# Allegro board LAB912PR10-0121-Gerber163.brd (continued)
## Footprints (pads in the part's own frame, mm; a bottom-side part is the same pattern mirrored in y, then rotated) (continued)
FIDUCIAL_C40M80
  round 1.016 smd: 1(0,0)
FOX_AS0A621-J4RB-7H_204P-T
  round 1.092 hole 1.092 unplated: (-65.05,-4.1)
  round 1.6 hole 1.6 unplated: (1.75,-4.1)
  oval 0.356x2.007 smd: 1(0,0) 2(-0.3,-8.2) 3(-0.6,0) 4(-0.9,-8.2) 5(-1.2,0) 6(-1.5,-8.2) 7(-1.8,0) 8(-2.1,-8.2) 9(-2.4,0) 10(-2.7,-8.2) 11(-3,0) 12(-3.3,-8.2) 13(-3.6,0) 14(-3.9,-8.2) 15(-4.2,0) 16(-4.5,-8.2) 17(-4.8,0) 18(-5.1,-8.2) 19(-5.4,0) 20(-5.7,-8.2) 21(-6,0) 22(-6.3,-8.2) 23(-6.6,0) 24(-6.9,-8.2) 25(-7.2,0) 26(-7.5,-8.2) 27(-7.8,0) 28(-8.1,-8.2) 29(-8.4,0) 30(-8.7,-8.2) 31(-9,0) 32(-9.3,-8.2) 33(-9.6,0) 34(-9.9,-8.2) 35(-10.2,0) 36(-10.5,-8.2) 37(-10.8,0) 38(-11.1,-8.2) 39(-11.4,0) 40(-11.7,-8.2) 41(-12,0) 42(-12.3,-8.2) 43(-12.6,0) 44(-12.9,-8.2) 45(-13.2,0) 46(-13.5,-8.2) 47(-13.8,0) 48(-14.1,-8.2) 49(-14.4,0) 50(-14.7,-8.2) 51(-15,0) 52(-15.3,-8.2) 53(-15.6,0) 54(-15.9,-8.2) 55(-16.2,0) 56(-16.5,-8.2) 57(-16.8,0) 58(-17.1,-8.2) 59(-17.4,0) 60(-17.7,-8.2) 61(-18,0) 62(-18.3,-8.2) 63(-18.6,0) 64(-18.9,-8.2) 65(-19.2,0) 66(-19.5,-8.2) 67(-19.8,0) 68(-20.1,-8.2) 69(-20.4,0) 70(-20.7,-8.2) 71(-21,0) 72(-21.3,-8.2) 73(-24,0) 74(-24.3,-8.2) 75(-24.6,0) 76(-24.9,-8.2) 77(-25.2,0) 78(-25.5,-8.2) 79(-25.8,0) 80(-26.1,-8.2) 81(-26.4,0) 82(-26.7,-8.2) 83(-27,0) 84(-27.3,-8.2) 85(-27.6,0) 86(-27.9,-8.2) 87(-28.2,0) 88(-28.5,-8.2) 89(-28.8,0) 90(-29.1,-8.2) 91(-29.4,0) 92(-29.7,-8.2) 93(-30,0) 94(-30.3,-8.2) 95(-30.6,0) 96(-30.9,-8.2) 97(-31.2,0) 98(-31.5,-8.2) 99(-31.8,0) 100(-32.1,-8.2) 101(-32.4,0) 102(-32.7,-8.2) 103(-33,0) 104(-33.3,-8.2) 105(-33.6,0) 106(-33.9,-8.2) 107(-34.2,0) 108(-34.5,-8.2) 109(-34.8,0) 110(-35.1,-8.2) 111(-35.4,0) 112(-35.7,-8.2) 113(-36,0) 114(-36.3,-8.2) 115(-36.6,0) 116(-36.9,-8.2) 117(-37.2,0) 118(-37.5,-8.2) 119(-37.8,0) 120(-38.1,-8.2) 121(-38.4,0) 122(-38.7,-8.2) 123(-39,0) 124(-39.3,-8.2) 125(-39.6,0) 126(-39.9,-8.2) 127(-40.2,0) 128(-40.5,-8.2) 129(-40.8,0) 130(-41.1,-8.2) 131(-41.4,0) 132(-41.7,-8.2) 133(-42,0) 134(-42.3,-8.2) 135(-42.6,0) 136(-42.9,-8.2) 137(-43.2,0) 138(-43.5,-8.2) 139(-43.8,0) 140(-44.1,-8.2) 141(-44.4,0) 142(-44.7,-8.2) 143(-45,0) 144(-45.3,-8.2) 145(-45.6,0) 146(-45.9,-8.2) 147(-46.2,0) 148(-46.5,-8.2) 149(-46.8,0) 150(-47.1,-8.2) 151(-47.4,0) 152(-47.7,-8.2) 153(-48,0) 154(-48.3,-8.2) 155(-48.6,0) 156(-48.9,-8.2) 157(-49.2,0) 158(-49.5,-8.2) 159(-49.8,0) 160(-50.1,-8.2) 161(-50.4,0) 162(-50.7,-8.2) 163(-51,0) 164(-51.3,-8.2) 165(-51.6,0) 166(-51.9,-8.2) 167(-52.2,0) 168(-52.5,-8.2) 169(-52.8,0) 170(-53.1,-8.2) 171(-53.4,0) 172(-53.7,-8.2) 173(-54,0) 174(-54.3,-8.2) 175(-54.6,0) 176(-54.9,-8.2) 177(-55.2,0) 178(-55.5,-8.2) 179(-55.8,0) 180(-56.1,-8.2) 181(-56.4,0) 182(-56.7,-8.2) 183(-57,0) 184(-57.3,-8.2) 185(-57.6,0) 186(-57.9,-8.2) 187(-58.2,0) 188(-58.5,-8.2) 189(-58.8,0) 190(-59.1,-8.2) 191(-59.4,0) 192(-59.7,-8.2) 193(-60,0) 194(-60.3,-8.2) 195(-60.6,0) 196(-60.9,-8.2) 197(-61.2,0) 198(-61.5,-8.2) 199(-61.8,0) 200(-62.1,-8.2) 201(-62.4,0) 202(-62.7,-8.2) 203(-63,0) 204(-63.3,-8.2)
  rect 3.505x4.597 smd: 205(-64.45,7.9) 206(1.15,7.9)
H_3P0
  round 3.505 hole 2.997: 1(0,0)
H_3P0X3P8N
  oval 2.997x3.81 hole 2.997x3.81 unplated: (0,0)
H_3P2
  round 3.708 hole 3.2: 1(0,0)
H_3P3
  round 3.81 hole 3.302: 1(0,0)
H_4P0N
  round 3.988 hole 3.988 unplated: (0,0)
INPAQ_HCM2012GA900AE_4P
  rect 0.762x0.508 smd: 1(0,0) 2(1.85,0) 3(1.85,-0.9) 4(0,-0.9)
IP4292CZ10-TBR_XSON10_2P5X1
  oval 0.254x0.889 smd: 1(0,0)
  oval 0.254x0.838 smd: 2(0.5,-0.025) 3(1,-0.025) 4(1.5,-0.025) 5(2,-0.025) 6(2,1.125) 7(1.5,1.125) 8(1,1.125) 9(0.5,1.125) 10(0,1.125)
ISL95833HRTZ-T_TQFN32_4X4
  oval 0.203x0.914 smd: 1(0,0) 2(0.4,0) 3(0.8,0) 4(1.2,0) 5(1.6,0) 6(2,0) 7(2.4,0) 8(2.8,0) 17(2.8,4.077) 18(2.4,4.077) 19(2,4.077) 20(1.6,4.077) 21(1.2,4.077) 22(0.8,4.077) 23(0.4,4.077) 24(0,4.077)
  oval 0.914x0.203 smd: 9(3.438,0.639) 10(3.438,1.039) 11(3.438,1.438) 12(3.438,1.838) 13(3.438,2.239) 14(3.438,2.639) 15(3.438,3.039) 16(3.438,3.438) 25(-0.639,3.438) 26(-0.639,3.039) 27(-0.639,2.639) 28(-0.639,2.239) 29(-0.639,1.838) 30(-0.639,1.438) 31(-0.639,1.039) 32(-0.639,0.639)
  rect 2.692x2.692 smd: 33(1.4,2.039)
JUMP_43X39
  custom 0.191x0.191 smd: 1(0,0) 2(0.914,0)
JUMP_43X79
  custom 0.188x0.188 smd: 1(0,0) 2(1.1,0)
JUMP_43X118
  custom 0.187x0.187 smd: 1(0,0) 2(1.1,0)
JXT_FP202DH-004M10M_4P
  oval 0.61x1.448 smd: 1(0,0) 2(1,0) 3(2,0) 4(3,0)
  rect 2.159x2.21 smd: 5(-2.825,-3.125) 6(5.825,-3.125)
JXT_FP202DH-008M10M_8P
  oval 0.61x1.448 smd: 1(0,0) 2(1,0) 3(2,0) 4(3,0) 5(4,0) 6(5,0) 7(6,0) 8(7,0)
  rect 2.159x2.21 smd: 9(-2.825,-3.125) 10(9.825,-3.125)
KB9022QC_LQFP128_14X14
  oval 1.753x0.203 smd: 1(0,0) 2(0,-0.4) 3(0,-0.8) 4(0,-1.2) 5(0,-1.6) 6(0,-2) 7(0,-2.4) 8(0,-2.8) 9(0,-3.2) 10(0,-3.6) 11(0,-4) 12(0,-4.4) 13(0,-4.8) 14(0,-5.2) 15(0,-5.6) 16(0,-6) 17(0,-6.4) 18(0,-6.8) 19(0,-7.2) 20(0,-7.6) 21(0,-8) 22(0,-8.4) 23(0,-8.8) 24(0,-9.2) 25(0,-9.6) 26(0,-10) 27(0,-10.4) 28(0,-10.8) 29(0,-11.2) 30(0,-11.6) 31(0,-12) 32(0,-12.4) 65(15.654,-12.4) 66(15.654,-12) 67(15.654,-11.6) 68(15.654,-11.2) 69(15.654,-10.8) 70(15.654,-10.4) 71(15.654,-10) 72(15.654,-9.6) 73(15.654,-9.2) 74(15.654,-8.8) 75(15.654,-8.4) 76(15.654,-8) 77(15.654,-7.6) 78(15.654,-7.2) 79(15.654,-6.8) 80(15.654,-6.4) 81(15.654,-6) 82(15.654,-5.6) 83(15.654,-5.2) 84(15.654,-4.8) 85(15.654,-4.4) 86(15.654,-4) 87(15.654,-3.6) 88(15.654,-3.2) 89(15.654,-2.8) 90(15.654,-2.4) 91(15.654,-2) 92(15.654,-1.6) 93(15.654,-1.2) 94(15.654,-0.8) 95(15.654,-0.4) 96(15.654,0)
  oval 0.203x1.753 smd: 33(1.627,-14.027) 34(2.027,-14.027) 35(2.427,-14.027) 36(2.827,-14.027) 37(3.227,-14.027) 38(3.627,-14.027) 39(4.027,-14.027) 40(4.427,-14.027) 41(4.827,-14.027) 42(5.227,-14.027) 43(5.627,-14.027) 44(6.027,-14.027) 45(6.427,-14.027) 46(6.827,-14.027) 47(7.227,-14.027) 48(7.627,-14.027) 49(8.027,-14.027) 50(8.427,-14.027) 51(8.827,-14.027) 52(9.227,-14.027) 53(9.627,-14.027) 54(10.027,-14.027) 55(10.427,-14.027) 56(10.827,-14.027) 57(11.227,-14.027) 58(11.627,-14.027) 59(12.027,-14.027) 60(12.427,-14.027) 61(12.827,-14.027) 62(13.227,-14.027) 63(13.627,-14.027) 64(14.027,-14.027) 97(14.027,1.627) 98(13.627,1.627) 99(13.227,1.627) 100(12.827,1.627) 101(12.427,1.627) 102(12.027,1.627) 103(11.627,1.627) 104(11.227,1.627) 105(10.827,1.627) 106(10.427,1.627) 107(10.027,1.627) 108(9.627,1.627) 109(9.227,1.627) 110(8.827,1.627) 111(8.427,1.627) 112(8.027,1.627) 113(7.627,1.627) 114(7.227,1.627) 115(6.827,1.627) 116(6.427,1.627) 117(6.027,1.627) 118(5.627,1.627) 119(5.227,1.627) 120(4.827,1.627) 121(4.427,1.627) 122(4.027,1.627) 123(3.627,1.627) 124(3.227,1.627) 125(2.827,1.627) 126(2.427,1.627) 127(2.027,1.627) 128(1.627,1.627)
KC_FBMA-L11-160808-800LMT_2P
  rect 0.889x1.092 smd: 1(0,0) 2(1.5,0)
KC_FBMA-L11-201209-221LMA30_2P
  rect 0.838x1.397 smd: 1(0,0) 2(1.65,0)
L_4X4X2_F_2P-NPM
  rect 1.194x3.708 smd: 1(0,0) 2(2.8,0)
L_7X7X3_M_2P
  rect 2.362x3.505 smd: 1(0,0) 2(6.05,0)
LBAV70WT1G_SC70-3
  oval 0.711x0.889 smd: 1(0,0) 2(-0.65,-1.9) 3(0.65,-1.9)
LED_12-21C-T3D-CM2P1B18X-2C_3P
  rect 0.991x0.787 smd: 1(0,0) 2(-2.8,0)
  rect 0.991x0.61 smd: 3(-1.4,0.4)
LED_12-22A-S2ST3D-C30-2C_3P
  rect 0.991x1.499 smd: 1(0,0) 3(-3,0)
  rect 0.889x0.889 smd: 2(-1.5,-0.65)
LOTES_AAA-BAT-054-K01_2P
  round 0.787 hole 0.787 unplated: (-14.5,-8)
  round 1.194 hole 1.194 unplated: (-14.5,8)
  rect 2.007x3.988 smd: 1(0,0) 2(-30.1,0)
MDV1527URH_POWERDFN33-8-5
  oval 0.406x0.61 smd: 1(0,0) 2(0.65,0) 3(1.3,0) 4(1.95,0)
  custom 0.65x0.65 smd: 5(0.975,1.475)
MDV1528URH_PDFN33-8-5
  oval 0.406x0.61 smd: 1(0,0) 2(0.65,0) 3(1.3,0) 4(1.95,0)
  custom 0.65x0.65 smd: 5(0.975,1.475)
MESS138W-G_SOT323-3
  oval 0.711x0.889 smd: 1(0,0) 2(-0.65,-1.9) 3(0.65,-1.9)
MMST3904-7-F_SOT323-3
  oval 0.711x0.889 smd: 1(0,0) 2(0.65,1.9) 3(-0.65,1.9)
MOLEX_52435-2671_26P-T
  oval 0.305x0.787 smd: 1(0,0) 2(0.5,0) 3(1,0) 4(1.5,0) 5(2,0) 6(2.5,0) 7(3,0) 8(3.5,0) 9(4,0) 10(4.5,0) 11(5,0) 12(5.5,0) 13(6,0) 14(6.5,0) 15(7,0) 16(7.5,0) 17(8,0) 18(8.5,0) 19(9,0) 20(9.5,0) 21(10,0) 22(10.5,0) 23(11,0) 24(11.5,0) 25(12,0) 26(12.5,0)
  custom 0.597x0.597 smd: 27(-2.45,-1.925) 28(14.95,-1.925)
MURAT_BLM15AG102SN1D_2P
  rect 0.457x0.508 smd: 1(0,0) 2(0.85,0)
MURAT_BLM15BB221SN1D_2P
  rect 0.508x0.762 smd: 1(0,0) 2(0.75,0)
MURAT_BLM15BD601SN1D_2P
  rect 0.508x0.762 smd: 1(0,0) 2(0.75,0)
MURAT_BLM41PG600SN1L_2P
  rect 1.194x2.108 smd: 1(0,0) 2(3.8,0)
MURAT_BLM41PG600SN1L_2P-NPM
  rect 1.194x2.108 smd: 1(0,0) 2(3.8,0)
NCT3942S_SO8
  oval 0.635x1.854 smd: 1(0,0) 2(1.27,0) 3(2.54,0) 4(3.81,0) 5(3.81,5.165) 6(2.54,5.165) 7(1.27,5.165) 8(0,5.165)
PANAS_ETQP4LR15AFM_4P
  custom 0.686x0.686 smd: 1(0,0) 4(8.357,0)
  rect 2.21x0.508 smd: 2(1.448,0) 3(6.909,0)
PESD5V0U2BT_SOT23-3
  oval 1.016x1.524 smd: 1(0,0) 2(0.965,2.083) 3(-0.965,2.083)
R0402_0OHM
  rect 0.508x0.559 smd: 1(0,0) 2(0.914,0)
R0603_0OHM
  rect 0.635x0.889 smd: 1(0,0) 2(1.397,0)
R0805_0OHM
  rect 0.813x1.397 smd: 1(0,0) 2(1.702,0)
R_0402
  rect 0.508x0.559 smd: 1(0,0) 2(0.914,0)
R_0603
  rect 0.635x0.889 smd: 1(0,0) 2(1.397,0)
R_1206
  rect 1.016x1.651 smd: 1(0,0) 2(2.667,0)
R_1206_4P-D
  custom 0.445x0.445 smd: 1(0,0) 4(5.004,0)
  custom 0.114x0.114 smd: 2(1.194,0) 3(3.81,0)
RB751V-40_SOD323-2
  rect 0.787x0.889 smd: 1(0,0) 2(2.14,0)
RHU002N06_SOT323-3
  oval 0.813x0.914 smd: 1(0,0) 2(0.65,1.6) 3(-0.65,1.6)
RP_0804_8P4R
  oval 0.66x0.254 smd: 1(0,0) 2(0,-0.5) 3(0,-1) 4(0,-1.5) 5(1.15,-1.5) 6(1.15,-1) 7(1.15,-0.5) 8(1.15,0)
RT8207MZQW_WQFN20_3X3
  oval 0.203x0.889 smd: 1(0,0) 2(0.4,0) 3(0.8,0) 4(1.2,0) 5(1.6,0) 11(1.6,3.1) 12(1.2,3.1) 13(0.8,3.1) 14(0.4,3.1) 15(0,3.1)
  oval 0.889x0.203 smd: 6(2.35,0.75) 7(2.35,1.15) 8(2.35,1.55) 9(2.35,1.95) 10(2.35,2.35) 16(-0.75,2.35) 17(-0.75,1.95) 18(-0.75,1.55) 19(-0.75,1.15) 20(-0.75,0.75)
  rect 1.702x1.702 smd: 21(0.8,1.55)
RTS5179-GR_QFN24_4X4
  oval 0.254x0.889 smd: 1(0,0) 2(0.5,0) 3(1,0) 4(1.5,0) 5(2,0) 6(2.5,0) 13(2.5,4.1) 14(2,4.1) 15(1.5,4.1) 16(1,4.1) 17(0.5,4.1) 18(0,4.1)
  oval 0.889x0.254 smd: 7(3.3,0.8) 8(3.3,1.3) 9(3.3,1.8) 10(3.3,2.3) 11(3.3,2.8) 12(3.3,3.3) 19(-0.8,3.3) 20(-0.8,2.8) 21(-0.8,2.3) 22(-0.8,1.8) 23(-0.8,1.3) 24(-0.8,0.8)
  rect 2.261x2.261 smd: 25(1.25,2.05)
SHORTPADS
  custom 0.19x0.19 smd: 1(-0.483,0) 2(0.483,0)
SI3456BDV-T1-E3_TSOP6
  oval 0.508x1.448 smd: 1(0,0) 2(1,0) 3(2,0) 4(2,2.425) 5(1,2.425) 6(0,2.425)
SI4459ADY-T1-GE3_SO8
  oval 0.635x1.727 smd: 1(0,0) 2(1.27,0) 3(2.54,0) 4(3.81,0) 5(3.81,5.285) 6(2.54,5.285) 7(1.27,5.285) 8(0,5.285)
SIS412DN-T1-GE3_POWERPAK8-5
  oval 0.406x0.991 smd: 1(0,0) 2(0.66,0) 3(1.32,0) 4(1.98,0)
  custom 0.559x0.559 smd: 5(0.99,2.247)
SN74LVC1G07DCKR_SC70-5
  oval 0.381x0.864 smd: 1(0,0) 2(0.65,0) 3(1.3,0) 4(1.3,1.74) 5(0,1.74)
SUYIN_200277GR008M270ZR_8P-T
  round 1.6 hole 0.991: 1(0,0) 2(2,0) 3(4,0) 4(6,0) 5(8,0) 6(10,0) 7(12,0) 8(14,0)
  oval 1.397x3.454 hole 0.787x2.845: 9(17.125,0) 10(-3.125,0)
SW_SMT1-05-A_4P
  rect 0.61x0.991 smd: 1(0,0) 2(0,-4.4) 3(3.7,0) 4(3.7,-4.4)
  rect 0.457x0.991 smd: 5(-0.675,-2.2) 6(4.375,-2.2)
SY6288C20AAC_SOT23-5
  oval 0.559x0.787 smd: 1(0,0) 2(0.95,0) 3(1.9,0) 4(1.9,2.4) 5(0,2.4)
SY6288D20AAC_SOT23-5
  oval 0.559x0.787 smd: 1(0,0) 2(0.95,0) 3(1.9,0) 4(1.9,2.4) 5(0,2.4)
SY8032ABC_SOT23-6
  oval 0.61x0.991 smd: 1(0,0) 2(0.95,0) 3(1.9,0) 4(1.9,2.4) 5(0.95,2.4) 6(0,2.4)
TAI-T_HCB2012KF-121T50_2P
  rect 0.991x0.991 smd: 1(0,0) 2(2,0)
TAI_PSDATG-11GLBS1NN4H0_11P-T
  round 1.194 hole 1.194 unplated: (-18.375,-2.925)
  round 1.702 hole 1.702 unplated: (2.625,-2.925)
  oval 0.991x1.753 smd: 1(0,0) 2(-2.5,0) 3(-5,0) 4(-7.5,0) 5(-10,0) 6(-12.5,0) 7(-15,0) 8(-16.63,0) 9(2.5,0)
  oval 0.711x1.753 smd: 10(-17.93,0) 11(-19.13,0)
  rect 1.473x2.794 smd: 12(-20.525,-1.925) 15(4.425,-1.925)
  oval 1.194x3.912 hole 0.61x3.404: 13(-19.975,-11.775) 14(6.225,-11.775)
TAITW_PUBAUN-09FLBS1NN4H0_9P-T
  round 1.295 hole 0.711: 1(0,0) 2(-2.5,0) 3(-4.5,0) 4(-7,0) 5(-7.5,-1.5) 6(-5.5,-1.5) 7(-3.5,-1.5) 8(-1.5,-1.5) 9(0.5,-1.5)
  oval 1.295x2.997 hole 0.711x2.388: 10(2.9,-0.75) 11(-9.9,-0.75)
  oval 1.295x2.21 hole 0.711x1.6: 12(-11.35,-9.2) 13(4.35,-9.2)
TCS20DLR_SOT23F-3
  oval 0.787x0.889 smd: 1(0,0) 2(-0.95,-2.1) 3(0.95,-2.1)
TOKO_1239AS-H-1R0M-P2_2P
  rect 0.787x2.007 smd: 1(0,0) 2(2,0)
TPC12
  round 0.305 smd: 1(0,0)
TPS51225CRUKR_QFN20_3X3
  oval 0.203x0.889 smd: 1(0,0) 2(0.4,0) 3(0.8,0) 4(1.2,0) 5(1.6,0) 11(1.6,3.1) 12(1.2,3.1) 13(0.8,3.1) 14(0.4,3.1) 15(0,3.1)
  oval 0.889x0.203 smd: 6(2.35,0.75) 7(2.35,1.15) 8(2.35,1.55) 9(2.35,1.95) 10(2.35,2.35) 16(-0.75,2.35) 17(-0.75,1.95) 18(-0.75,1.55) 19(-0.75,1.15) 20(-0.75,0.75)
  rect 1.702x1.702 smd: 21(0.8,1.55)
TVNST52302AB0_SOT523-3
  oval 0.508x0.559 smd: 1(0,0) 2(-0.5,-1.4) 3(0.5,-1.4)
W25Q64DWSSIG_SO8
  oval 0.635x1.676 smd: 1(0,0) 2(1.27,0) 3(2.54,0) 4(3.81,0) 5(3.81,7.25) 6(2.54,7.25) 7(1.27,7.25) 8(0,7.25)
Y_5YEA12000122IFA2Q3_4P
  rect 1.295x1.194 smd: 1(0,0) 2(2.2,0) 3(2.2,1.7) 4(0,1.7)
Y_7V25000014_4P
  rect 1.397x1.194 smd: 1(0,0) 2(2.2,0) 3(2.2,1.7) 4(0,1.7)
Y_CM7V-12520_2P
  rect 0.991x1.803 smd: 1(0,0) 2(2.5,0)
YSLC05CH_SOT23-3
  oval 1.016x1.524 smd: 1(0,0) 2(0.965,2.083) 3(-0.965,2.083)

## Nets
1.0VS_GATE: C1131.1 Q70.1 R1061.1 U60.4
1.8VS_ON: C1125.2 R1055.1 U12.2
1.35VS_ON: C1128.2 R1056.1 U12.4
3VS_ON: C980.1 R927.1 U11.2
5VS_ON: C979.2 R926.2 U11.4
+0.675VS: CD24.1 CD25.1 CD26.1 CD27.1 CD28.1 CD29.1 CD43.1 CD44.1 CD45.1 CD46.1 JDIMM2.203 JDIMM2.204 PJP202.2 R2314.1
+0.675VSP: PC208.1 PC209.1 PJP202.1 PU200.2 PU200.20
+1.0VALW: C1034.2 C1035.2 C1036.2 C1037.2 C1039.2 C1074.1 C1129.2 PJP303.2 U60.5 U60.6 U60.7 U60.8 USOC1.B6 USOC1.C3 USOC1.C5 USOC1.U22 USOC1.V18 USOC1.V22 USOC1.Y19
+1.0VALWP: PC308.1 PC310.1 PC311.1 PJP303.1 PL301.2 PR307.1
+1.0VALWP_ON: PC309.1 PR305.1 PR308.2 PU301.1
+1.0VS: C1043.2 C1044.2 C1046.2 C1047.2 C1048.2 C1049.2 C1050.2 C1052.2 C1056.2 C1057.2 C1059.2 C1060.2 C1061.2 C1062.2 C1064.2 C1066.2 C1068.2 C1069.2 C1070.2 C1071.2 C1072.2 C1130.2 PC523.1 PR525.2 PR526.2 PR527.2 R1052.2 RC15.2 RC27.1 U60.1 U60.2 U60.3 USOC1.AA36 USOC1.AD35 USOC1.AF16 USOC1.AF18 USOC1.AF21 USOC1.AF35 USOC1.AF36 USOC1.AG21 USOC1.AJ18 USOC1.AJ36 USOC1.AK18 USOC1.AK19 USOC1.AK21 USOC1.AK35 USOC1.AK36 USOC1.AM16 USOC1.AM18 USOC1.AM21 USOC1.AN18 USOC1.AN19 USOC1.AN21 USOC1.AN25 USOC1.AN29 USOC1.AN30 USOC1.BJ6 USOC1.G1 USOC1.M14 USOC1.U18 USOC1.U19 USOC1.V24 USOC1.V32 USOC1.Y18 USOC1.Y22 USOC1.Y24 USOC1.Y35 USOC1.Y36
+1.0VS_R: Q71.1 R1052.1
+1.05V_PGOOD: T210.1(TP-1) UE1.106
+1.05VS: C1038.1 C1040.1 C1041.1 C1042.1 PJP301.2 R2315.1 RC100.1 USOC1.AA33 USOC1.AF33 USOC1.AG33 USOC1.AG35 USOC1.U33 USOC1.U35 USOC1.V33
+1.5VS: C1058.1 PJP405.2 RA8.1 UA1.9 USOC1.AM32
+1.05VS_SOC: RC100.2 USOC1.AC32 USOC1.Y32
+1.5VSP: PC413.1 PC414.1 PJP405.1 PR410.1 PU402.3 PU402.4
+1.05VSP: PC301.1 PC302.1 PC303.1 PJP301.1 PL300.2 PR302.1
+1.05VSP_ON: PC304.1 PR300.2 PR303.1 PU300.1
+1.8VALW: C1045.1 C1145.2 JDB1.16 PJP401.2 PJP404.1 R3.1 R4.1 R7.1 R32.2 R34.2 R36.2 RC21.1 RC44.1 RC46.1 RC61.1 RC62.1 RC63.1 RC65.1 RC99.1 RE21.1 RE25.1 RE34.1 RP65.5 RP65.6 RP65.7 RP65.8 RP66.1 RP66.2 U12.1 UC5.5 USOC1.AA18 USOC1.N20 USOC1.U24 USOC1.U25 USOC1.V25
+1.8VALWP: PC401.1 PC402.1 PC403.1 PJP401.1 PL400.2 PR402.1
+1.8VS: C1051.1 C1053.1 C1054.1 C1055.1 C1147.1 JP38.2 Q57.2 Q58.2 QC2.2 QC3.2 QC4.2 QE7.2 QE8.2 QE10.2 QE11.2 QE12.2 R8.1 R376.1 R3406.1 RC8.2 RC10.1 RC16.1 RC17.1 RC18.1 RC43.1 RC102.1 RE30.1 RE31.1 RP15.3 RP15.4 RP63.5 RP63.6 RP63.7 RP63.8 RP68.5 RP68.6 RP68.7 RX2.1 RX3.1 RX41.1 UC10.5 USOC1.AM30 USOC1.AN32 USOC1.U38
+1.8VS_OUT: C1124.2 JP38.1 U12.10
+1.8VSP_ON: PC404.1 PR400.2 PR403.1 PU400.1
+1.35V: C1146.2 CD4.1 CD5.1 CD6.1 CD7.1 CD8.1 CD9.1 CD10.1 CD11.1 CD12.1 CD13.1 CD14.1 CD15.1 CD16.1 CD17.1 CD18.1 CD19.1 CD20.1 CD33.1 CD34.1 CD35.1 CD36.1 CD37.1 CD38.1 CD39.1 CD40.1 CD41.1 CD42.1 CD62.2 JDIMM2.75 JDIMM2.76 JDIMM2.81 JDIMM2.82 JDIMM2.87 JDIMM2.88 JDIMM2.93 JDIMM2.94 JDIMM2.99 JDIMM2.100 JDIMM2.105 JDIMM2.106 JDIMM2.111 JDIMM2.112 JDIMM2.117 JDIMM2.118 JDIMM2.123 JDIMM2.124 JP14.2 JP15.2 PC902.1 PC904.1 PC906.1 PC908.1 PJP201.2 R1027.1 R1029.1 RC6.1 RD3.1 U12.5
+1.35V_SOC: CC29.2 CC30.2 CC31.2 CC32.2 CC33.1 CC34.1 JP14.1 JP15.1 RC54.1 USOC1.A48 USOC1.AK38 USOC1.AM38 USOC1.AV41 USOC1.AV42 USOC1.BB46 USOC1.BD49 USOC1.BD52 USOC1.BD53 USOC1.BF44 USOC1.BG51 USOC1.BJ48 USOC1.C51 USOC1.D44 USOC1.F49 USOC1.F52 USOC1.F53 USOC1.H46 USOC1.M41 USOC1.M42 USOC1.V38 USOC1.Y38
+1.35VP: PC201.1 PC216.2 PJP201.1 PL200.1 PR204.2 PR210.1 PU200.5 PU200.19
+1.35VS: C1148.1 CC38.1 CC39.1 CC40.1 CC41.1 CC42.1 CC43.1 CC44.1 CC45.1 CC46.1 CC47.1 JP39.2 RC30.1 RC67.1 USOC1.AA25 USOC1.AD36 USOC1.AF19 USOC1.AG18 USOC1.AG19 USOC1.AG32 USOC1.AJ19 USOC1.U36 USOC1.V36
+1.35VS_OUT: C1126.2 JP39.1 U12.6
+3V_HUB: R1047.1 R1050.1 R1051.1
+3VALW: C1143.2 C2316.1 C2318.1 CE61.2 PJP101.2 PJP300.1 PJP302.1 PJP400.1 PR4.2 PR7.2 PR510.1 PR530.2 R1022.1 R2356.2 RA17.1 RE2.2 RE6.2 U11.1 UC7.5
+3VALW_EC: C1.1 C2.1 CE1.1 CE2.1 CE5.2 CE6.2 JPWR.1 LE1.1 R1.1 R488.1 R696.2 R697.2 RE3.2 RE6.1 RE11.2 RP36.5 RP36.6 U70.2 UE1.22 UE1.33 UE1.96 UE1.125
+3VALW_SOC: C1063.1 C1065.1 C1067.1 R1022.2 USOC1.N18 USOC1.N22 USOC1.P18
+3VALWP: PC102.1 PC106.1 PJP101.1 PL100.1 PR100.1 PR106.1
+3VLP: JP12.1 PC105.1 PU100.3 RE49.2 UE1.111
+3VS: C1075.1 C2323.1 C2324.1 C2498.1 CA57.1 CA58.1 CA59.1 CA60.1 CD30.1 CD31.1 CD47.1 CD62.1 CX7.1 JDIMM2.199 JP36.2 Q14.5 Q6103.2 R9.2 R11.2 R122.1 R1023.1 R2448.1 R2449.1 R2451.1 R6110.1 RA1.1 RA2.1 RA18.2 RA54.2 RA155.2 RC20.1 RC53.1 RC68.1 RE50.1 RM7.1 RP36.7 RP36.8 RP54.5 RP54.6 RP54.7 RP54.8 RR9.2 RS7.1 RT17.1 RV299.2 RX10.1 RX12.1 RX27.2 U2407.1 UA1.1 UA1.36 UX4.5
+3VS_CAM: JEDP.32 RX27.1
+3VS_CARD: CR1.1 CR2.1 RR9.1 UR1.4
+3VS_LCDIN: CX9.1 RV299.1 UX1.4 UX1.5
+3VS_OUT: C1138.2 JP36.1 U11.10
+3VS_SOC: R1023.2 USOC1.AN24 USOC1.AN27
+3VS_TP: CE59.1 JTP.1 RE9.1 RE10.1 RE17.1 RE19.1 RE20.1 RE26.2 RE28.1 UE4.7 UE4.8
+3VS_TPIN: RE2.1 RE26.1 UE4.1 UE4.2 UE4.4
+3VS_WLAN_NGFF: CM4.1 CM5.1 CM6.1 CM7.1 CM8.1 CM9.1 JNGFF.2 JNGFF.4 JNGFF.64 JNGFF.66 QM30.2 R490.1 RM7.2 RM110.1
+5V_AUDIO: CA51.1 CA71.1 RV59.2 UA1.26
+5V_HDD: CS5.1 CS6.1 CS7.1 JHDD.1 JHDD.2 JHDD.3 JP13.1
+5V_HUB: C1117.1 C1118.1 R1045.2 R1046.1 R1053.2 U58.20
+5V_PVDD: CA53.1 CA54.1 CA55.1 CA56.1 RV54.2 UA1.41 UA1.46
+5V_USB_PWR1: CI1.1 CI2.1 CI40.1 JUSB1.1 UI5.1
+5V_USB_PWR2: CI19.1 JIO1.11 JIO1.12 JIO1.13 JIO1.14 JIO1.15 R1053.1 UI4.1
+5VALW: C1120.1 C1144.2 C2305.1 C2306.1 CI6.1 CI7.1 CI12.1 CI14.1 CI18.1 PC411.1 PC715.1 PJP100.2 PR3.1 PR203.1 PR209.1 PR518.2 PR519.1 PR524.1 PU402.6 PU700.11 Q6101.3 Q6102.3 R10.1 R1045.1 R1061.2 U11.3 U11.5 U12.3 UI4.5 UI5.5
+5VALWP: PC103.1 PC107.2 PJP100.1 PL101.2 PR101.2 PU100.14
+5VS: C2307.1 C2308.1 CE25.1 CS13.1 FX1.2 JP7.1 JP13.2 JP37.2 Q6104.3 QS2.1 QS2.2 QS2.5 QS2.6 RE60.1 RV54.1 RV59.1 RX28.2 UE3.1 UE3.2
+5VS_ODD: CS10.1 CS11.1 CS12.1 JODD1.10 JODD1.11 JODD1.12 JODD1.13 JODD1.14 JODD1.15 RS12.2
+5VS_ODD_R1: JP7.2 QS2.4 RS12.1
+5VS_OUT: C1139.2 JP37.1 U11.6
+5VS_TOUCH: CX49.1 CX50.1 JEDP.40 RX24.1 RX30.1 RX39.1 RX40.1 RX42.1 UX3.1
+V18R: CE16.1 RE21.2 UE1.124
+VCC_3IN1: CR7.1 CR8.1 JREAD.4 UR1.5
+VCC_LPC: RE25.2 UE1.9
+VCC_LPC_SOC: C1073.1 RC102.2 USOC1.AM27
B+_3/5V: PC108.1 PC109.1 PC110.1 PC111.1 PJP102.2 PL102.2 PQ101.5 PQ102.5 PR111.1
GND: C1.2 C2.2 C3.1 C967.1 C976.1 C979.1 C980.2 C1034.1 C1035.1 C1036.1 C1037.1 C1038.2 C1039.1 C1040.2 C1041.2 C1042.2 C1043.1 C1044.1 C1045.2 C1046.1 C1047.1 C1048.1 C1049.1 C1050.1 C1051.2 C1052.1 C1053.2 C1054.2 C1055.2 C1056.1 C1057.1 C1058.2 C1059.1 C1060.1 C1061.1 C1062.1 C1063.2 C1064.1 C1065.2 C1066.1 C1067.2 C1068.1 C1069.1 C1070.1 C1071.1 C1072.1 C1073.2 C1074.2 C1075.2 C1076.2 C1078.2 C1117.2 C1118.2 C1119.2 C1120.2 C1121.2 C1122.1 C1123.1 C1124.1 C1125.1 C1126.1 C1127.1 C1128.1 C1129.1 C1130.1 C1131.2 C1132.2 C1133.2 C1138.1 C1139.1 C1143.1 C1144.1 C1145.1 C1146.1 C1147.2 C1148.2 C2305.2 C2306.2 C2307.2 C2308.2 C2316.2 C2318.2 C2323.2 C2324.2 C2498.2 CA1.2 CA2.2 CA21.2 CA22.2 CA25.1 CA29.2 CA30.2 CA31.2 CA32.2 CA53.2 CA54.2 CA55.2 CA56.2 CA57.2 CA58.2 CA59.2 CA60.2 CA64.1 CA69.2 CC1.2 CC2.2 CC7.2 CC8.1 CC9.2 CC10.2 CC11.2 CC12.2 CC13.2 CC14.2 CC15.2 CC16.2 CC17.2 CC18.2 CC19.2 CC20.1 CC21.2 CC22.2 CC23.2 CC24.1 CC25.2 CC26.2 CC27.2 CC28.2 CC29.1 CC30.1 CC31.1 CC32.1 CC33.2 CC34.2 CC35.2 CC36.2 CC38.2 CC39.2 CC40.2 CC41.2 CC42.2 CC43.2 CC44.2 CC45.2 CC46.2 CC47.2 CC49.2 CC50.2 CC51.2 CC52.2 CC53.2 CC54.2 CC56.2 CC57.2 CC59.2 CC61.2 CC63.2 CC65.2 CD1.2 CD2.2 CD3.2 CD4.2 CD5.2 CD6.2 CD7.2 CD8.2 CD9.2 CD10.2 CD11.2 CD12.2 CD13.2 CD14.2 CD15.2 CD16.2 CD17.2 CD18.2 CD19.2 CD20.2 CD21.2 CD22.2 CD24.2 CD25.2 CD26.2 CD27.2 CD28.2 CD29.2 CD30.2 CD31.2 CD32.2 CD33.2 CD34.2 CD35.2 CD36.2 CD37.2 CD38.2 CD39.2 CD40.2 CD41.2 CD42.2 CD43.2 CD44.2 CD45.2 CD46.2 CD47.2 CE1.2 CE2.2 CE5.1 CE6.1 CE8.2 CE10.2 CE12.2 CE16.2 CE18.1 CE20.2 CE23.2 CE24.2 CE25.2 CE26.2 CE27.2 CE28.2 CE29.2 CE31.2 CE32.2 CE34.2 CE35.2 CE36.2 CE59.2 CE60.2 CE61.1 CI1.2 CI2.2 CI6.2 CI7.2 CI12.2 CI13.2 CI14.2 CI15.2 CI17.2 CI18.2 CI19.2 CI26.2 CI40.2 CLIP1.1(TP-1) CLIP2.1(TP-1) CLIP3.1(TP-1) CLRP1.2 CM4.2 CM5.2 CM6.2 CM7.2 CM8.2 CM9.2 CR1.2 CR2.2 CR3.1 CR4.1 CR6.2 CR7.2 CR8.2 CR9.2 CR11.2 CS5.2 CS6.2 CS7.2 CS10.2 CS11.2 CS12.2 CS13.2 CS16.2 CS17.2 CX5.2 CX6.2 CX7.2 CX8.2 CX9.2 CX10.2 CX11.2 CX21.2 CX22.2 CX49.2 CX50.2 CX51.2 CX52.2 D25.1 D26.1 D27.1 DE3.1 DI1.3 DI1.8 EC6104.2 H1.1(TP-1) H3.1(TP-1) H4.1(TP-1) H5.1(TP-1) H6.1(TP-1) H9.1(TP-1) H10.1(TP-1) H11.1(TP-1) H12.1(TP-1) JDB1.3 JDB1.6 JDB1.9 JDB1.19 JDB1.25 JDB1.27 JDB1.28 JDIMM2.2 JDIMM2.3 JDIMM2.8 JDIMM2.9 JDIMM2.13 JDIMM2.14 JDIMM2.19 JDIMM2.20 JDIMM2.25 JDIMM2.26 JDIMM2.31 JDIMM2.32 JDIMM2.37 JDIMM2.38 JDIMM2.43 JDIMM2.44 JDIMM2.48 JDIMM2.49 JDIMM2.54 JDIMM2.55 JDIMM2.60 JDIMM2.61 JDIMM2.65 JDIMM2.66 JDIMM2.71 JDIMM2.72 JDIMM2.127 JDIMM2.128 JDIMM2.133 JDIMM2.134 JDIMM2.138 JDIMM2.139 JDIMM2.144 JDIMM2.145 JDIMM2.150 JDIMM2.151 JDIMM2.155 JDIMM2.156 JDIMM2.161 JDIMM2.162 JDIMM2.167 JDIMM2.168 JDIMM2.172 JDIMM2.173 JDIMM2.178 JDIMM2.179 JDIMM2.184 JDIMM2.185 JDIMM2.189 JDIMM2.190 JDIMM2.195 JDIMM2.196 JDIMM2.205 JDIMM2.206 JEDP.13 JEDP.16 JEDP.19 JEDP.23 JEDP.24 JEDP.25 JEDP.29 JEDP.36 JEDP.41 JEDP.42 JFAN.3 JFAN.4 JFAN.5 JHDD.6 JHDD.9 JHDD.12 JHDD.13 JHDD.14 JHDMI1.2 JHDMI1.5 JHDMI1.8 JHDMI1.11 JHDMI1.17 JHDMI1.20 JHDMI1.21 JHDMI1.22 JHDMI1.23 JIO1.17 JIO1.20 JIO1.23 JIO1.24 JIO1.25 JIO1.26 JKB.31 JKB.32 JNGFF.1 JNGFF.7 JNGFF.10 JNGFF.18 JNGFF.25 JNGFF.31 JNGFF.37 JNGFF.43 JNGFF.49 JNGFF.55 JNGFF.61 JNGFF.67 JNGFF.68 JNGFF.69 JODD1.1 JODD1.4 JODD1.7 JODD1.18 JODD1.19 JODD1.20 JODD1.21 JODD1.22 JPWR.4 JPWR.5 JPWR.6 JREAD.3 JREAD.6 JREAD.12 JREAD.13 JREAD.14 JREAD.15 JRTC.2 JSPK.5 JSPK.6 JTP.4 JTP.9 JTP.10 JUSB1.4 JUSB1.7 JUSB1.10 JUSB1.11 JUSB1.12 JUSB1.13 LE2.1 LED1.3 LED2.1 PBATT1.1 PBATT1.2 PBATT1.3 PBATT1.9 PBATT1.10 PC1.2 PC2.2 PC3.2 PC4.2 PC5.2 PC6.2 PC7.2 PC8.2 PC9.2 PC10.2 PC12.2 PC102.2 PC103.2 PC105.2 PC108.2 PC109.2 PC110.2 PC111.2 PC114.2 PC115.2 PC116.2 PC117.2 PC118.2 PC201.2 PC203.2 PC204.2 PC205.2 PC206.2 PC208.2 PC209.2 PC210.1 PC211.2 PC212.2 PC213.2 PC214.2 PC215.2 PC300.1 PC302.2 PC303.2 PC304.2 PC305.2 PC306.2 PC307.1 PC308.2 PC309.2 PC311.2 PC400.1 PC402.2 PC403.2 PC404.2 PC405.2 PC411.2 PC412.2 PC414.2 PC415.2 PC501.2 PC502.2 PC503.1 PC508.2 PC509.2 PC510.2 PC511.2 PC512.2 PC516.2 PC517.1 PC518.2 PC519.2 PC520.2 PC521.2 PC522.2 PC523.2 PC525.1 PC526.2 PC533.1 PC534.2 PC535.1 PC536.2 PC702.2 PC703.2 PC704.2 PC705.2 PC706.2 PC707.2 PC708.2 PC710.2 PC711.2 PC712.1 PC714.2 PC715.2 PC716.2 PC717.2 PC718.2 PC719.2 PC720.2 PC721.2 PC723.2 PC725.1 PC726.2 PC727.2 PC901.1 PC902.2 PC903.1 PC904.2 PC905.1 PC906.2 PC907.1 PC908.2 PC909.2 PC911.2 PC913.1 PC914.1 PC915.1 PC916.1 PC917.2 PC918.2 PC919.2 PC920.1 PC921.1 PC922.1 PC923.1 PC924.1 PC925.1 PC926.1 PC927.1 PC928.1 PC929.1 PC930.1 PC931.1 PC932.1 PC933.1 PC934.1 PD1.1 PD2.1 PH1.2 PH501.1 PH502.1 PJP1.2 PJPDC1.7 PJPDC1.8 PL2.2 PQ2.3 PQ3.1 PQ3.4 PQ4.1 PQ4.4 PQ10.1 PQ10.4 PQ103.1 PQ103.2 PQ103.3 PQ104.1 PQ104.2 PQ104.3 PQ203.1 PQ203.2 PQ203.3 PQ501.5 PQ501.6 PQ501.7 PQ503.5 PQ503.6 PQ503.7 PQ703.1 PQ703.2 PQ703.3 PQ708.3 PQ709.1 PQ709.4 PQ710.1 PQ710.4 PQ711.3 PQ712.3 PQ713.1 PQ713.4 PR5.1 PR19.1 PR20.2 PR21.2 PR26.2 PR35.2 PR102.1 PR103.2 PR104.1 PR105.2 PR116.2 PR117.2 PR206.2 PR303.2 PR304.2 PR305.2 PR309.2 PR403.2 PR404.2 PR411.2 PR412.2 PR508.2 PR514.1 PR529.2 PR534.1 PR715.1 PR716.2 PR728.1 PR729.1 PU100.21 PU200.1 PU200.3 PU200.14 PU200.21 PU300.2 PU301.2 PU400.2 PU402.1 PU500.33 PU700.12 PU700.14 PU700.19 PU700.29 Q8.3 Q9.3 Q14.1 Q14.4 Q70.3 Q71.3 Q2307.3 Q2308.3 QA5.1 QA5.4 QC1.3 QS3.3 R16.2 R121.2 R122.2 R1024.2 R1028.1 R1030.1 R1033.2 R1048.2 R3405.2 RA19.2 RA29.2 RA30.2 RA31.2 RA32.2 RA81.1 RC1.1 RC2.1 RC3.1 RC4.1 RC5.1 RC7.1 RC11.2 RC14.2 RC22.1 RC23.1 RC26.2 RC32.1 RC40.2 RC41.1 RC42.1 RC45.1 RC47.1 RC48.2 RC49.1 RC50.1 RC57.2 RC58.2 RC59.2 RC60.1 RD6.1 RD7.1 RE1.1 RE5.1 RE7.1 RE18.2 RM11.1 RP1.1 RP1.2 RP1.3 RP66.3 RP66.4 RR1.2 RS9.1 RT18.2 RX9.2 RX20.2 RX23.2 RX26.2 SW1.1 SW1.2 SW1.5 SW1.6 SW2.1 SW2.2 SW2.5 SW2.6 U11.8 U11.11 U12.8 U12.11 U58.1 U68.3 U69.3 U70.1 U2407.6 UA1.4 UA1.49 UC5.3 UC7.3 UC8.4 UC10.3 UE1.11 UE1.24 UE1.35 UE1.94 UE1.113 UE3.5 UE3.6 UE3.7 UE3.8 UE4.5 UE4.9 UI4.2 UI5.2 UR1.25 USOC1.A3 USOC1.A5 USOC1.A6 USOC1.A11 USOC1.A15 USOC1.A19 USOC1.A23 USOC1.A27 USOC1.A31 USOC1.A35 USOC1.A39 USOC1.A43 USOC1.A47 USOC1.A49 USOC1.A51 USOC1.A52 USOC1.AA1 USOC1.AA3 USOC1.AA16 USOC1.AA19 USOC1.AA21 USOC1.AA32 USOC1.AA35 USOC1.AA38 USOC1.AA53 USOC1.AB4 USOC1.AB6 USOC1.AB10 USOC1.AB41 USOC1.AB45 USOC1.AB47 USOC1.AB48 USOC1.AB50 USOC1.AB51 USOC1.AC16 USOC1.AC18 USOC1.AC19 USOC1.AC21 USOC1.AC25 USOC1.AC33 USOC1.AC35 USOC1.AC36 USOC1.AC38 USOC1.AD7 USOC1.AD16 USOC1.AD18 USOC1.AD19 USOC1.AD21 USOC1.AD25 USOC1.AD32 USOC1.AD33 USOC1.AD47 USOC1.AE1 USOC1.AE3 USOC1.AE4 USOC1.AE6 USOC1.AE8 USOC1.AE9 USOC1.AE11 USOC1.AE12 USOC1.AE14 USOC1.AE40 USOC1.AE42 USOC1.AE43 USOC1.AE45 USOC1.AE46 USOC1.AE48 USOC1.AE50 USOC1.AE51 USOC1.AE53 USOC1.AF10 USOC1.AF12 USOC1.AF25 USOC1.AF32 USOC1.AF47 USOC1.AG16 USOC1.AG25 USOC1.AG36 USOC1.AG38 USOC1.AH2 USOC1.AH3 USOC1.AH4 USOC1.AH6 USOC1.AH7 USOC1.AH9 USOC1.AH41 USOC1.AH45 USOC1.AH47 USOC1.AH48 USOC1.AH50 USOC1.AH51 USOC1.AJ1 USOC1.AJ3 USOC1.AJ16 USOC1.AJ21 USOC1.AJ25 USOC1.AJ27 USOC1.AJ29 USOC1.AJ30 USOC1.AJ32 USOC1.AJ33 USOC1.AJ35 USOC1.AJ38 USOC1.AJ53 USOC1.AK10 USOC1.AK14 USOC1.AK16 USOC1.AK33 USOC1.AK41 USOC1.AK44 USOC1.AM2 USOC1.AM3 USOC1.AM7 USOC1.AM12 USOC1.AM19 USOC1.AM24 USOC1.AM25 USOC1.AM29 USOC1.AM33 USOC1.AM35 USOC1.AM36 USOC1.AM40 USOC1.AM44 USOC1.AM51 USOC1.AN1 USOC1.AN3 USOC1.AN5 USOC1.AN6 USOC1.AN8 USOC1.AN9 USOC1.AN11 USOC1.AN12 USOC1.AN14 USOC1.AN16 USOC1.AN22 USOC1.AN33 USOC1.AN35 USOC1.AN36 USOC1.AN38 USOC1.AN40 USOC1.AN42 USOC1.AN43 USOC1.AN45 USOC1.AN46 USOC1.AN48 USOC1.AN49 USOC1.AN51 USOC1.AN53 USOC1.AP40 USOC1.AT4 USOC1.AT12 USOC1.AT16 USOC1.AT19 USOC1.AT24 USOC1.AT27 USOC1.AT30 USOC1.AT35 USOC1.AT38 USOC1.AT47 USOC1.AT52 USOC1.AU1 USOC1.AU3 USOC1.AU24 USOC1.AU30 USOC1.AU38 USOC1.AU51 USOC1.AV7 USOC1.AV12 USOC1.AV13 USOC1.AV14 USOC1.AV18 USOC1.AV19 USOC1.AV24 USOC1.AV27 USOC1.AV30 USOC1.AV35 USOC1.AV38 USOC1.AV47 USOC1.AV51 USOC1.AW3 USOC1.AW13 USOC1.AW19 USOC1.AW27 USOC1.AW35 USOC1.AY4 USOC1.AY9 USOC1.AY10 USOC1.AY22 USOC1.AY32 USOC1.AY36 USOC1.AY50 USOC1.B2 USOC1.B52 USOC1.B53 USOC1.BA14 USOC1.BA19 USOC1.BA22 USOC1.BA27 USOC1.BA32 USOC1.BA35 USOC1.BA40 USOC1.BA53 USOC1.BB5 USOC1.BB7 USOC1.BB10 USOC1.BB19 USOC1.BB27 USOC1.BB35 USOC1.BC1 USOC1.BC2 USOC1.BC10 USOC1.BC20 USOC1.BC22 USOC1.BC26 USOC1.BC28 USOC1.BC32 USOC1.BC34 USOC1.BC42 USOC1.BD19 USOC1.BD24 USOC1.BD27 USOC1.BD30 USOC1.BD35 USOC1.BE1 USOC1.BE2 USOC1.BE8 USOC1.BE19 USOC1.BE35 USOC1.BE53 USOC1.BF4 USOC1.BF12 USOC1.BF16 USOC1.BF24 USOC1.BF30 USOC1.BF36 USOC1.BF38 USOC1.BG1 USOC1.BG31 USOC1.BG34 USOC1.BG39 USOC1.BG42 USOC1.BG45 USOC1.BG49 USOC1.BG53 USOC1.BH1 USOC1.BH2 USOC1.BH52 USOC1.BH53 USOC1.BJ2 USOC1.BJ3 USOC1.BJ5 USOC1.BJ7 USOC1.BJ11 USOC1.BJ15 USOC1.BJ19 USOC1.BJ23 USOC1.BJ27 USOC1.BJ31 USOC1.BJ35 USOC1.BJ39 USOC1.BJ43 USOC1.BJ47 USOC1.BJ49 USOC1.BJ51 USOC1.BJ52 USOC1.C1 USOC1.C14 USOC1.C31 USOC1.C34 USOC1.C39 USOC1.C42 USOC1.C45 USOC1.C49 USOC1.C53 USOC1.D12 USOC1.D16 USOC1.D24 USOC1.D30 USOC1.D36 USOC1.D38 USOC1.E1 USOC1.E8 USOC1.E19 USOC1.E35 USOC1.E53 USOC1.F2 USOC1.F5 USOC1.F7 USOC1.F19 USOC1.F24 USOC1.F27 USOC1.F30 USOC1.F35 USOC1.G10 USOC1.G20 USOC1.G22 USOC1.G26 USOC1.G28 USOC1.G32 USOC1.G34 USOC1.G42 USOC1.H19 USOC1.H27 USOC1.H35 USOC1.J1 USOC1.J16 USOC1.J19 USOC1.J22 USOC1.J27 USOC1.J32 USOC1.J35 USOC1.J40 USOC1.J53 USOC1.K4 USOC1.K9 USOC1.K14 USOC1.K22 USOC1.K32 USOC1.K36 USOC1.K50 USOC1.L13 USOC1.L19 USOC1.L27 USOC1.L35 USOC1.M19 USOC1.M26 USOC1.M27 USOC1.M28 USOC1.M34 USOC1.M35 USOC1.M38 USOC1.M47 USOC1.M51 USOC1.N1 USOC1.N16 USOC1.N38 USOC1.N51 USOC1.P4 USOC1.P9 USOC1.P13 USOC1.P16 USOC1.P19 USOC1.P20 USOC1.P24 USOC1.P32 USOC1.P35 USOC1.P38 USOC1.P47 USOC1.P52 USOC1.T40 USOC1.U1 USOC1.U3 USOC1.U5 USOC1.U6 USOC1.U8 USOC1.U9 USOC1.U11 USOC1.U12 USOC1.U14 USOC1.U16 USOC1.U21 USOC1.U30 USOC1.U32 USOC1.U40 USOC1.U42 USOC1.U43 USOC1.U45 USOC1.U46 USOC1.U48 USOC1.U49 USOC1.U51 USOC1.U53 USOC1.V7 USOC1.V12 USOC1.V16 USOC1.V19 USOC1.V21 USOC1.V35 USOC1.V40 USOC1.V44 USOC1.V51 USOC1.Y7 USOC1.Y9 USOC1.Y10 USOC1.Y14 USOC1.Y16 USOC1.Y21 USOC1.Y25 USOC1.Y33 USOC1.Y41 USOC1.Y44 UX1.2 UX3.2 UX4.2 YC1.2 YC1.4
GNDA: CA23.1 CA51.2 CA61.2 CA62.1 CA63.1 CA71.2 CA74.2 JIO1.1 JIO1.9 QA1.1 QA1.4 RA20.2 RA29.1 RA30.1 RA31.1 RA32.1 RA83.2 RA84.2 RA154.1 UA1.25 UA1.38
V1: PQ708.2 PQ709.6 PQ713.6 PR702.2 PR714.2
V18: CR4.2 UR1.24
VCCST_PG_EC: CE35.1 T209.1(TP-1) UE1.21
VDD_1.35VP: PC213.1 PR201.1 PR203.2 PU200.11
VDDP_LDO: PC714.1 PR709.1 PR710.1 PU700.21
VIN: PC3.1 PC4.1 PL1.2 PQ704.5 PQ704.6 PQ704.7 PQ704.8 PR12.1 PR14.2 PR702.1 PR706.2 PR707.1 PR711.2 PR730.1
+BIOS_SPI: CC21.1 RC36.1 RC37.1 RC38.1 RC99.2 UC8.8
+CHGRTC: DC3.2 JP12.2
+CODEC_AVDD2: CA61.1 RA8.2 UA1.40
+DDR_SOC_VREF: CC2.1 RC6.2 RC7.2 USOC1.AF44
+DIMM1_VREF_CA: C1078.1 R1029.2 R1030.2 RD4.2
+DIMM1_VREF_DQ: C1076.1 CD1.1 CD2.1 JDIMM2.1 R1027.2 R1028.2
+EC_VCCA: CE7.1 LE1.2 PR10.1 UE1.67
+FAN_POWER: CE23.1 CE24.1 JFAN.1 UE3.3
+INV_PWR_SRC: CX5.1 FX2.1 JEDP.1 JEDP.2
+LCDVDD: LX1.1 UX1.1 UX4.1
+LCDVDD_CONN: CX8.1 CX11.1 JEDP.4 JEDP.5 JEDP.6 JEDP.7 LX1.2
+MIC2-VREFO: RA53.2 RA1109.2 UA1.29
+RTCBATT: JRTC.1 RC33.2
+RTCBATT_R: DC3.3 RC33.1
+RTCVCC: CC23.1 DC3.1 RA16.1 RC34.1 RC35.1 USOC1.P22
+SOC_VCC: CD32.1 PC901.2 PC903.2 PC905.2 PC907.2 PC909.1 PC911.1 PC929.2 PC930.2 PC931.2 PC932.2 PC933.2 PC934.2 PL501.4 RC56.1 USOC1.AA27 USOC1.AA29 USOC1.AA30 USOC1.AC27 USOC1.AC29 USOC1.AC30 USOC1.AD27 USOC1.AD29 USOC1.AD30 USOC1.AF27 USOC1.AF29 USOC1.AG27 USOC1.AG29 USOC1.AG30 USOC1.P26 USOC1.P27 USOC1.U27 USOC1.U29 USOC1.V27 USOC1.V29 USOC1.V30 USOC1.Y27 USOC1.Y29 USOC1.Y30
+SOC_VNN: PC913.2 PC914.2 PC915.2 PC916.2 PC917.1 PC918.1 PC919.1 PC920.2 PC921.2 PC922.2 PC923.2 PC924.2 PC925.2 PC926.2 PC927.2 PC928.2 PL500.4 RC55.1 USOC1.AA24 USOC1.AC22 USOC1.AC24 USOC1.AD22 USOC1.AD24 USOC1.AF22 USOC1.AF24 USOC1.AG22 USOC1.AG24 USOC1.AJ22 USOC1.AJ24 USOC1.AK22 USOC1.AK24 USOC1.AK25 USOC1.AK27 USOC1.AK29 USOC1.AK30 USOC1.AK32 USOC1.AM22
+V_TS: CX6.1 CX51.1 RX28.1 RX30.2 UX3.5
+VDISPLAY_VCC: CX21.1 CX22.1 FX1.1 JHDMI1.18 RP15.1 RP15.2
ACIN: CE18.2 DC1.1 PR16.1 PR710.2 PR712.1 PR716.1 PU700.13 UE1.110
ACIN_65W: T221.1(TP-1) UE1.108
ACOFF: PQ713.5 PR718.1 UE1.27
ACSETIN: PC712.2 PR711.1 PR715.2 PU700.2
AD_BID0: CE8.1 RE3.1 RE5.2 UE1.66
AD_BID1: CE10.1 RE7.2 RE11.1 UE1.75
AD_I_HW1: PQ10.2 UE1.36
AD_I_HW2: PQ10.5 UE1.34
ADP_I: PC725.2 PR11.1 PR722.1 UE1.65
ADPIN: PC1.1 PC2.1 PJPDC1.5 PJPDC1.6 PL1.1
AUD_HP_OUT_L_CN: JIO1.8 LA8.2
AUD_HP_OUT_R_CN: JIO1.7 LA9.2
B+: CX10.1 FX2.2 PJP102.1 PJP200.1 PJP500.2 PJP700.1 PL102.1 PL502.2 PL701.1 PQ706.1 PQ706.2 PQ706.3 PR34.2 PR700.4 RS6.2
B+_1.35VP: PC203.1 PC204.1 PC205.1 PC206.1 PJP200.2 PQ201.5 PR205.1
BAT_AMBER: LED1.1 R6103.1
BAT_WHITE: LED1.2 R6107.1
BATT+: PC5.1 PC717.1 PC718.1 PC719.1 PC720.1 PJP4.1 PL4.1 PQ706.5 PQ706.6 PQ706.7 PQ706.8 PR720.4 PR726.2
BATT++: PBATT1.7 PBATT1.8 PC6.1 PJP4.2 PL4.2
BATT_LOW_LED: Q6101.1 R6103.2
BATT_LOW_LED#: R6105.2 UE1.93
BATT_LOW_LED_R#: Q6101.2 R6105.1
BATT_PRS: PBATT1.4 PR6.1
BATT_TEMP: CE9.2 PC11.1 PC708.1 PD2.2 PQ710.2 PQ710.5 PQ713.2 PR6.2 PR7.1 UE1.63
BEEP#: DA8.2 UE1.23
BKOFF#: DX1.2 RX25.1 UE1.105
BOOT1: PR531.1 PU500.16
BOOT_1.35VP: PR200.2 PU200.18
BOOTG: PR511.1 PU500.26
BST: PR713.2 PU700.25
BST_1.35VP: PC207.1 PR200.1
BST_3V: PR107.2 PU100.9
BST_5V: PR108.1 PU100.17
BST_CHGA: PC713.1 PR713.1
BT_ON#: RM9.2 RP54.2 USOC1.AT28
CAPS_LED: JKB.1 UE1.91
CHG: PL700.2 PR720.1
CHG_B+: PC702.1 PC703.1 PC704.1 PC705.1 PJP700.2 PL701.2 PQ701.5
CLK_PCIE_WLAN: RI5.2 USOC1.AF7
CLK_PCIE_WLAN#: RI6.2 USOC1.AF9
CLK_PCIE_WLAN#_R: JNGFF.41 RI6.1
CLK_PCIE_WLAN_R: JNGFF.39 RI5.1
CLK_SMB: PBATT1.6 PR8.1
CLR_CMOS: CLRP1.1 R1088.1 R1089.1
CPU_B+: PC501.1 PC508.1 PC509.1 PC510.1 PC519.1 PC521.1 PC522.1 PC536.1 PJP500.1 PL502.1 PQ501.2 PQ501.3 PQ501.4 PQ501.10 PQ503.2 PQ503.3 PQ503.4 PQ503.10
CPU_DPB_CTRLCLK_R: JHDMI1.15 Q57.1 RP15.8
CPU_DPB_CTRLDAT_R: JHDMI1.16 Q58.1 RP15.7
CPU_EDP_AUX#_C: CX43.2 JEDP.12 RT17.2
CPU_EDP_AUX_C: CX44.2 JEDP.11 RT18.1
CPU_EDP_N0_C: CX46.2 JEDP.14
CPU_EDP_N1_C: CX47.2 JEDP.17
CPU_EDP_P0_C: CX42.2 JEDP.15
CPU_EDP_P1_C: CX45.2 JEDP.18
CS1: PR105.1 PU100.1
CS2: PR104.2 PU100.5
CS_1.35VP: PR201.2 PU200.13
CSIN: PR700.3 PR705.1
CSIP: PR700.2 PR704.1
DAT_SMB: PBATT1.5 PR9.1
DBC_EN: RX19.2 UE1.89
DBC_EN_R: JEDP.8 RX19.1 RX23.1
DBG_UART_RXD: T107.1(TP-1) USOC1.BC16
DBG_UART_TXD: T106.1(TP-1) USOC1.BD14
DCIN: PC711.1 PR707.2 PU700.22
DDI0_RCOMPN: RC9.1 USOC1.AK13
DDI0_RCOMPP: RC9.2 USOC1.AK12
DDI1_ENABLE: RC8.1 USOC1.P30
DDI1_ENBKL: R28.2 RP1.8 USOC1.J30
DDI1_ENVDD: R30.1 RP1.7 U68.2 USOC1.N30
DDI1_PWM: RP1.6 U69.2 USOC1.M30
DDR_A_BS0: JDIMM2.109 USOC1.K47
DDR_A_BS1: JDIMM2.108 USOC1.K44
DDR_A_BS2: JDIMM2.79 USOC1.D52
DDR_A_CAS#: JDIMM2.115 USOC1.M44
DDR_A_CKE0: JDIMM2.73 USOC1.C47
DDR_A_CKE2: JDIMM2.74 USOC1.F44
DDR_A_CLK0: JDIMM2.101 USOC1.M50
DDR_A_CLK0#: JDIMM2.103 USOC1.M48
DDR_A_CLK2: JDIMM2.102 USOC1.P50
DDR_A_CLK2#: JDIMM2.104 USOC1.P48
DDR_A_CS0#: JDIMM2.114 USOC1.P44
DDR_A_CS2#: JDIMM2.121 USOC1.P45
DDR_A_D0: JDIMM2.5 USOC1.M36
DDR_A_D1: JDIMM2.7 USOC1.J36
DDR_A_D2: JDIMM2.15 USOC1.P40
DDR_A_D3: JDIMM2.17 USOC1.M40
DDR_A_D4: JDIMM2.4 USOC1.P36
DDR_A_D5: JDIMM2.6 USOC1.N36
DDR_A_D6: JDIMM2.16 USOC1.K40
DDR_A_D7: JDIMM2.18 USOC1.K42
DDR_A_D8: JDIMM2.21 USOC1.B32
DDR_A_D9: JDIMM2.23 USOC1.C32
DDR_A_D10: JDIMM2.33 USOC1.C36
DDR_A_D11: JDIMM2.35 USOC1.A37
DDR_A_D12: JDIMM2.22 USOC1.C33
DDR_A_D13: JDIMM2.24 USOC1.A33
DDR_A_D14: JDIMM2.34 USOC1.C37
DDR_A_D15: JDIMM2.36 USOC1.B38
DDR_A_D16: JDIMM2.39 USOC1.F36
DDR_A_D17: JDIMM2.41 USOC1.G38
DDR_A_D18: JDIMM2.51 USOC1.F42
DDR_A_D19: JDIMM2.53 USOC1.J42
DDR_A_D20: JDIMM2.40 USOC1.G40
DDR_A_D21: JDIMM2.42 USOC1.C38
DDR_A_D22: JDIMM2.50 USOC1.G44
DDR_A_D23: JDIMM2.52 USOC1.D42
DDR_A_D24: JDIMM2.57 USOC1.A41
DDR_A_D25: JDIMM2.59 USOC1.C41
DDR_A_D26: JDIMM2.67 USOC1.A45
DDR_A_D27: JDIMM2.69 USOC1.B46
DDR_A_D28: JDIMM2.56 USOC1.C40
DDR_A_D29: JDIMM2.58 USOC1.B40
DDR_A_D30: JDIMM2.68 USOC1.B48
DDR_A_D31: JDIMM2.70 USOC1.B47
DDR_A_D32: JDIMM2.129 USOC1.K52
DDR_A_D33: JDIMM2.131 USOC1.K51
DDR_A_D34: JDIMM2.141 USOC1.T52
DDR_A_D35: JDIMM2.143 USOC1.T51
DDR_A_D36: JDIMM2.130 USOC1.L51
DDR_A_D37: JDIMM2.132 USOC1.L53
DDR_A_D38: JDIMM2.140 USOC1.R51
DDR_A_D39: JDIMM2.142 USOC1.R53
DDR_A_D40: JDIMM2.147 USOC1.T47
DDR_A_D41: JDIMM2.149 USOC1.T45
DDR_A_D42: JDIMM2.157 USOC1.Y40
DDR_A_D43: JDIMM2.159 USOC1.V41
DDR_A_D44: JDIMM2.146 USOC1.T48
DDR_A_D45: JDIMM2.148 USOC1.T50
DDR_A_D46: JDIMM2.158 USOC1.Y42
DDR_A_D47: JDIMM2.160 USOC1.AB40
DDR_A_D48: JDIMM2.163 USOC1.V45
DDR_A_D49: JDIMM2.165 USOC1.V47
DDR_A_D50: JDIMM2.175 USOC1.AD48
DDR_A_D51: JDIMM2.177 USOC1.AD50
DDR_A_D52: JDIMM2.164 USOC1.V48
DDR_A_D53: JDIMM2.166 USOC1.V50
DDR_A_D54: JDIMM2.174 USOC1.AB44
DDR_A_D55: JDIMM2.176 USOC1.Y45
DDR_A_D56: JDIMM2.181 USOC1.V52
DDR_A_D57: JDIMM2.183 USOC1.W51
DDR_A_D58: JDIMM2.191 USOC1.AC53
DDR_A_D59: JDIMM2.193 USOC1.AC51
DDR_A_D60: JDIMM2.180 USOC1.W53
DDR_A_D61: JDIMM2.182 USOC1.Y51
DDR_A_D62: JDIMM2.192 USOC1.AD52
DDR_A_D63: JDIMM2.194 USOC1.AD51
DDR_A_DM0: JDIMM2.11 USOC1.G36
DDR_A_DM1: JDIMM2.28 USOC1.B36
DDR_A_DM2: JDIMM2.46 USOC1.F38
DDR_A_DM3: JDIMM2.63 USOC1.B42
DDR_A_DM4: JDIMM2.136 USOC1.P51
DDR_A_DM5: JDIMM2.153 USOC1.V42
DDR_A_DM6: JDIMM2.170 USOC1.Y50
DDR_A_DM7: JDIMM2.187 USOC1.Y52
DDR_A_DQS0: JDIMM2.12 USOC1.J38
DDR_A_DQS1: JDIMM2.29 USOC1.C35
DDR_A_DQS2: JDIMM2.47 USOC1.D40
DDR_A_DQS3: JDIMM2.64 USOC1.B44
DDR_A_DQS4: JDIMM2.137 USOC1.N53
DDR_A_DQS5: JDIMM2.154 USOC1.T42
DDR_A_DQS6: JDIMM2.171 USOC1.Y47
DDR_A_DQS7: JDIMM2.188 USOC1.AB52
DDR_A_DQS#0: JDIMM2.10 USOC1.K38
DDR_A_DQS#1: JDIMM2.27 USOC1.B34
DDR_A_DQS#2: JDIMM2.45 USOC1.F40
DDR_A_DQS#3: JDIMM2.62 USOC1.C43
DDR_A_DQS#4: JDIMM2.135 USOC1.M52
DDR_A_DQS#5: JDIMM2.152 USOC1.T44
DDR_A_DQS#6: JDIMM2.169 USOC1.Y48
DDR_A_DQS#7: JDIMM2.186 USOC1.AA51
DDR_A_MA0: JDIMM2.98 USOC1.K45
DDR_A_MA1: JDIMM2.97 USOC1.H47
DDR_A_MA2: JDIMM2.96 USOC1.L41
DDR_A_MA3: JDIMM2.95 USOC1.H44
DDR_A_MA4: JDIMM2.92 USOC1.H50
DDR_A_MA5: JDIMM2.91 USOC1.G53
DDR_A_MA6: JDIMM2.90 USOC1.H49
DDR_A_MA7: JDIMM2.86 USOC1.D50
DDR_A_MA8: JDIMM2.89 USOC1.G52
DDR_A_MA9: JDIMM2.85 USOC1.E52
DDR_A_MA10: JDIMM2.107 USOC1.K48
DDR_A_MA11: JDIMM2.84 USOC1.E51
DDR_A_MA12: JDIMM2.83 USOC1.F47
DDR_A_MA13: JDIMM2.119 USOC1.J51
DDR_A_MA14: JDIMM2.80 USOC1.B49
DDR_A_MA15: JDIMM2.78 USOC1.B50
DDR_A_ODT0: RD8.2 USOC1.T41
DDR_A_ODT2: RD9.2 USOC1.P42
DDR_A_RAS#: JDIMM2.110 USOC1.M45
DDR_A_RST#: CD3.1 JDIMM2.30 RD5.1
DDR_A_RST#_CPU: RD3.2 RD5.2 USOC1.P41
DDR_A_WE#: JDIMM2.113 USOC1.H51
DDR_CORE_PWROK: CC1.1 CC19.1 RC30.2 UC7.4 USOC1.AB42
DDR_PWROK: PR210.2 PU200.10 USOC1.AD42
DDR_RCOMP0: RC3.2 USOC1.AD44
DDR_RCOMP1: RC4.2 USOC1.AF45
DDR_RCOMP2: RC5.2 USOC1.AD45
DDR_TERMN0: RC1.2 USOC1.AF42
DDR_TERMN1: RC2.2 USOC1.AH42
DEVSLP0: RC53.2 RS8.1 UC10.4
DEVSLP0_R: JHDD.5 RS8.2
DEVSLP_SOC: UC10.2 USOC1.AY14
DH_1.35VP: PQ201.4 PU200.17
DH_CHG: PQ701.4 PU700.24
DISPOFF#: DX1.1 JEDP.21 RX9.1 RX25.2
DL_1.35VP: PQ203.4 PU200.15
DL_CHG: PQ703.4 PU700.20
DRAM_VDD_S4_CLK: CC27.1 CC28.1 RC54.2 USOC1.AD38 USOC1.AF38
E51_RX2: JNGFF.50 T15.1(TP-1)
EC_LID_OUT#: R26.2 UE1.101
EC_MUTE#: RA54.1 UA1.47 UE1.83
EC_ON: PR115.1 UE1.112
EC_RSMRST#: CC14.1 CC54.1 JDB1.10 RC26.1 UE1.100 USOC1.B10
EC_RX: JNGFF.32 UE1.31
EC_SCI#: R29.2 UE1.20
EC_SMB_CK1: PD1.3 PR8.2 PR717.1 RP36.4 UE1.77
EC_SMB_CK2: JDIMM2.202 QC3.1 RE15.1 RE33.1 RP36.2
EC_SMB_CK2_EC: RE15.2 RE22.2 UE1.79
EC_SMB_DA1: PD1.2 PR9.2 PR719.1 RP36.3 UE1.78
EC_SMB_DA2: JDIMM2.200 QC4.1 RE16.1 RE32.1 RP36.1
EC_SMB_DA2_EC: RE16.2 RE23.2 UE1.80
EC_SMI#: R31.2 R488.2 UE1.15
EC_TP_INT#: RE29.1 UE1.74
EC_TX: JNGFF.30 RM11.2 UE1.30
ECAGND: CE7.2 CE9.1 LE2.2 UE1.69
EDP_CPU_AUX: CX44.1 USOC1.AK3
EDP_CPU_AUX#: CX43.1 USOC1.AK2
EDP_CPU_HPD: Q9.1 R3406.2 USOC1.K30
EDP_CPU_LANE_N0: CX46.1 USOC1.AG1
EDP_CPU_LANE_N1: CX47.1 USOC1.AF2
EDP_CPU_LANE_P0: CX42.1 USOC1.AG3
EDP_CPU_LANE_P1: CX45.1 USOC1.AF3
EDP_HPD: JEDP.9 Q9.2 R3405.1
EN_0.675VSP: PC215.1 PR208.2 PU200.7
EN_1.35VP: PC214.1 PR207.2 PU200.8
EN_3V: PR113.1 PU100.6
EN_5V: PR112.1 PU100.20
EN_5V3V: PC118.1 PR112.2 PR113.2 PR114.2 PR115.2 PR116.1
EN_DFAN1: UE1.70 UE3.4
EN_INVPWR: T197.1(TP-1) UE1.68
ENVDD: R11.1 R30.2 RX7.2 U68.4
ENVDD_R: RX7.1 UX1.3 UX4.4
ERP_LOT6: PC8.1 PQ3.2 PR16.2 PR21.1 UE1.73
FAN_SPEED1: CE29.1 CE32.1 JFAN.2 RE50.2 UE1.28
FB_1.0VALWP: PC310.2 PR307.2 PR309.1 PU301.6
FB_1.05VSP: PC301.2 PR302.2 PR304.1 PU300.6
FB_1.35VP: PC216.1 PR204.1 PR206.1 PU200.6
FB_3V: PC106.2 PR100.2 PR102.2 PU100.4
FB_5V: PC107.1 PR101.1 PR103.1 PU100.2
FB_+1.8VSP: PC401.2 PR402.2 PR404.1 PU400.6
GPIO_NC12: T98.1(TP-1) USOC1.B30
GPIO_NC13: RC10.2 RC11.1 USOC1.A29
GPIO_NC14: T97.1(TP-1) USOC1.C29
GPIO_RCOMP: RC32.2 USOC1.N26
GPIO_S0_SC_56: RC43.2 RC48.1 USOC1.BC12
GPIO_S0_SC_63: RC16.2 USOC1.BA30
GPIO_S0_SC_65: QC1.1 RC17.2 USOC1.BC30
GPIO_S0_SC_92: T110.1(TP-1) USOC1.BH30
GPIO_S0_SC_93: T111.1(TP-1) USOC1.BG30
GPIO_S5_14: RP65.3 USOC1.J20
GPIO_S5_17: T104.1(TP-1) USOC1.J24
H_PROCHOT#: CC8.2 PQ4.3 PQ4.6 R44.2 RC15.1 RE13.1 USOC1.C24
HDA_BIT_CLK: RP64.6 USOC1.BJ21
HDA_BITCLK_AUDIO: CC7.1 R2355.1 RP64.3 UA1.6
HDA_RCOMP: RC14.1 USOC1.BF20
HDA_RST#: RP64.5 USOC1.BG22
HDA_RST_AUDIO#: RP64.4 UA1.11
HDA_SDIN0: RA130.1 USOC1.BG19
HDA_SDOUT: RP64.7 USOC1.BG20
HDA_SDOUT_AUDIO: RP64.2 UA1.5
HDA_SYNC: RP64.8 USOC1.BH20
HDA_SYNC_AUDIO: RP64.1 UA1.10
HDMI_CLK+: CX13.2 USOC1.AP3
HDMI_CLK-: CX12.2 USOC1.AP2
HDMI_DDCCLK: Q57.3 RP15.6 USOC1.C28
HDMI_DDCDATA: Q58.3 RP15.5 USOC1.C26
HDMI_GND: Q14.3 R1071.2 R1072.2 R1073.2 R1074.2 R1075.2 R1076.2 R1077.2 R1078.2
HDMI_HPD#: Q14.6 R376.2 USOC1.D27
HDMI_HPLUG: JHDMI1.19 Q14.2 R121.1
HDMI_TX0+: CX15.2 USOC1.AR3
HDMI_TX0-: CX14.2 USOC1.AR1
HDMI_TX1+: CX17.2 USOC1.AT2
HDMI_TX1-: CX16.2 USOC1.AT3
HDMI_TX2+: CX19.2 USOC1.AV3
HDMI_TX2-: CX18.2 USOC1.AV2
HPOUT-L: RA55.1 UA1.32
HPOUT-R: RA56.1 UA1.33
HSIC_RCOMP: RC49.2 USOC1.A7
HUB_BUSJ: C1122.2 R1047.2 U58.17 U58.18 U58.19
HUB_OVCJ: C1121.1 R1046.2 R1051.2 U58.26
HUB_XIN: C1133.1 RC69.2 U58.3 Y9.3
HUB_XOUT: R1049.1 U58.2
I2C1_SCL: T114.1(TP-1) USOC1.BH24
I2C1_SDA: T113.1(TP-1) USOC1.BG24
I2C2_SCL_TP: QE8.3 RE30.2 USOC1.BJ25
I2C2_SCL_TP_R: JTP.3 QE8.1 RE19.2 RE33.2
I2C2_SDA_TP: QE7.3 RE31.2 USOC1.BG25
I2C2_SDA_TP_R: JTP.2 QE7.1 RE17.2 RE32.2
I2C5_SCL_PNL: QE11.3 RX3.2 USOC1.BG28
I2C5_SCL_PNL_R: QE11.1 RX39.2 T99.1(TP-1)
I2C5_SDA_PNL: QE10.3 RX2.2 USOC1.BH28
I2C5_SDA_PNL_R: QE10.1 RX40.2 T109.1(TP-1)
ICLK_ICOMP: RC23.2 USOC1.AD14
ICLK_RCOMP: RC22.2 USOC1.AD13
ICLK_USB_TERMN: RC42.2 USOC1.F10
ICLK_USB_TERMP: RC41.2 USOC1.D10
ILB_RTC_EXTPAD: CC15.1 USOC1.B8
ILB_RTC_X1: CC18.1 RC31.2 USOC1.C9 YC2.2
ILB_RTC_X2: CC17.1 RC31.1 USOC1.A9 YC2.1
INT-SPK-L+: LA5.2 UA1.42
INT-SPK-L-: LA6.2 UA1.43
INT-SPK-R+: LA3.2 UA1.45
INT-SPK-R-: LA4.2 UA1.44
INVT_PWM: JEDP.20 R9.1 RX26.1 U69.4
ISL88731_ICREF: PR727.1 PR729.2 PU700.1
ISL88731_VREF: PR725.2 PR727.2 PU700.3
JACK_PLUG#: JIO1.2 RA1.2 RA3.1 RA4.2
JACK_SENSE#: QA5.3 RA4.1 RA34.2
JHDD_P10: JHDD.4 RS7.2
KB_CAPS_PWR: JKB.4 RE60.2
KB_RST#: R22.2 UE1.2
KSI0: JKB.22 UE1.55
KSI1: JKB.24 UE1.56
KSI2: JKB.26 UE1.57
KSI3: JKB.23 UE1.58
KSI4: JKB.27 UE1.59
KSI5: JKB.25 UE1.60
KSI6: JKB.28 UE1.61
KSI7: JKB.29 UE1.62
KSO0: JKB.13 UE1.39
KSO1: JKB.15 UE1.40
KSO2: JKB.14 UE1.41
KSO3: JKB.16 UE1.42
KSO4: JKB.20 UE1.43
KSO5: JKB.21 UE1.44
KSO6: JKB.18 UE1.45
KSO7: JKB.19 UE1.46
KSO8: JKB.17 UE1.47
KSO9: JKB.7 UE1.48
KSO10: JKB.5 UE1.49
KSO11: JKB.6 UE1.50
KSO12: JKB.12 UE1.51
KSO13: JKB.9 UE1.52
KSO14: JKB.8 UE1.53
KSO15: JKB.10 UE1.54
KSO16: JKB.11 UE1.81
LAN_CLKREQ#: RP63.1 USOC1.BG3
LCD_TEST: JEDP.10 UE1.72
LG_3V: PQ103.4 PU100.11
LG_5V: PQ104.4 PU100.15
LGATE1: PQ503.8 PU500.19
LGATEG: PQ501.8 PU500.23
LID_SW#: C3.2 D2401.1 JPWR.3 R1.2 U70.3 UE1.115
LINE1-L: CA67.1 UA1.22
LINE1-R: CA68.1 UA1.21
LINE1-VREFO-L: RA165.1 UA1.31
LINE1-VREFO-R: RA166.1 UA1.30
LINE-IN-L: LA8.1 RA55.2 RA80.2 RA83.1 RA165.2
LINE-IN-R: LA9.1 RA56.2 RA82.2 RA84.1 RA166.2
LPC_AD0: UE1.10 USOC1.BH16
LPC_AD1: UE1.8 USOC1.BJ17
LPC_AD2: UE1.7 USOC1.BJ13
LPC_AD3: UE1.5 USOC1.BG14
LPC_CLK_0: CC25.1 RC51.2 USOC1.BG15
LPC_CLK_1: CC26.1 RC52.2 USOC1.BH14
LPC_CLK_EC: R2354.2 RC51.1 UE1.12
LPC_CLKRUN#: RC60.2 RX4.1 USOC1.BG16
LPC_FRAME#: UE1.4 USOC1.BG17
LPC_RCOMP: RC50.2 USOC1.BF18
LX_1.0VALWP: PL301.1 PR306.1 PU301.3
LX_1.05VSP: PL300.1 PR301.1 PU300.3
LX_3V: PC112.1 PL100.2 PQ101.1 PQ101.2 PQ101.3 PQ103.5 PR109.1 PU100.8
LX_5V: PC113.2 PL101.1 PQ102.1 PQ102.2 PQ102.3 PQ104.5 PR110.1 PU100.18
LX_+1.8VSP: PL400.1 PR401.1 PU400.3
LX_CHG: PC713.2 PL700.1 PQ701.1 PQ701.2 PQ701.3 PQ703.5 PR721.1 PU700.23
M_ODT0: JDIMM2.116 RD8.1
M_ODT1: JDIMM2.120 RD9.1
MAINPWON: R2450.2 T217.1(TP-1)
MIC1-L: CA74.1 UA1.19
MIC_CLK: JEDP.27 LA1.2
MIC_CLK_C: CA22.1 LA1.1 UA1.3
MIC_DATA: JEDP.28 UA1.2
MIC_GND: JEDP.26 RX20.1
MMC1_RCOMP: RC57.1 USOC1.AY18
MS_CLK_SD_WP: JREAD.11 UR1.8
MS_D1_SD_D3: JREAD.1 UR1.20
MS_D2_SD_CLK: CR6.1 JREAD.5 RR2.2
MS_D2_SD_CLK_R: RR2.1 UR1.15
NGFF_BT_ON#: JNGFF.46 RM9.1
NTC: PR523.1 PU500.7
NTC_1: PH502.2 PR523.2 PR529.1
NTCG: PR515.2 PU500.1
NTCG_1: PH501.2 PR514.2 PR515.1
ODD_DA#: DX2.1 RP54.1 RS10.1
ODD_DETECT#: RC68.2 RS09.1 USOC1.AU28
ODD_EN: CS16.1 QS2.3 QS3.1 RS6.1 RS9.2
ODD_EN#: QS3.2 USOC1.BD26
ON/OFFBTN#: CE20.1 JPWR.2 RE49.1 SW1.3 SW1.4 SW2.3 SW2.4 UE1.114
P2: PC700.1 PQ704.1 PQ704.2 PQ704.3 PQ705.1 PQ705.2 PQ705.3 PQ707.3 PR701.1
P3: PC701.2 PQ705.5 PQ705.6 PQ705.7 PQ705.8 PR700.1
PANEL_BKLEN: R28.1 UE1.76
PBTN_OUT#: R27.2 UE1.122
PC_BEEP: DA8.1 RA19.1 RA79.2
PCH_USB3_RX0_N: R2367.2 USOC1.E3
PCH_USB3_RX0_P: R2366.2 USOC1.D4
PCH_USB3_TX0_N: CI3.2 USOC1.K7
PCH_USB3_TX0_N_C: CI3.1 R2369.2
PCH_USB3_TX0_P: CI4.2 USOC1.K6
PCH_USB3_TX0_P_C: CI4.1 R2368.2
PCIE_CLKREQ_2#: RP63.3 USOC1.BG5
PCIE_PRX_DTX_N1: JNGFF.35 USOC1.AT9
PCIE_PRX_DTX_P1: JNGFF.33 USOC1.AT10
PCIE_PTX_C_DRX_N1: CC6.2 JNGFF.29
PCIE_PTX_C_DRX_P1: CC5.2 JNGFF.27
PCIE_PTX_DRX_N1: CC6.1 USOC1.AV4
PCIE_PTX_DRX_P1: CC5.1 USOC1.AV6
PCIE_RCOMPN: RC13.2 USOC1.AP13
PCIE_RCOMPP: RC13.1 USOC1.AP14
PCU_SMB_ALERT#: RP68.2 USOC1.BG11
PCU_SMB_CLK: QC3.3 RP68.4 USOC1.BH10
PCU_SMB_DATA: QC4.3 RP68.3 USOC1.BG12
PECI_KB9012: RE43.1 UE1.118
PHASE1: PC524.2 PL501.1 PQ503.9 PR532.1 PU500.18
PHASEG: PC515.2 PL500.1 PQ501.9 PR512.1 PU500.24
PLT_RST#: CC11.1 CE36.1 JNGFF.44 RC20.2 UC5.4 UE1.13
PMC_ACIN: DC1.2 RC21.2 USOC1.D20
PMC_BATLOW#: RP65.2 USOC1.K26
PMC_CORE_PWROK: CC16.1 CC57.1 CE31.1 JDB1.12 RE18.1 UC7.2 UE1.32 USOC1.B7
PMC_PCIE_WAKE#: RP65.1 USOC1.F26
PMC_PLTRST#: CC13.1 CC51.1 JDB1.17 UC5.2 USOC1.F20
PMC_PWRBTN#: R27.1 USOC1.J26
PMC_RSTBTN#: RC24.1 USOC1.BG9
PMC_SLP_S3#: R24.2 R1024.1 USOC1.D22
PMC_SLP_S4#: R25.2 R1033.1 USOC1.F22
PMC_SUSCLK: RM8.2 USOC1.G24
PS_ID: PR1.2 PR4.1 UE1.16
PSID: PJPDC1.3 PL3.2
PSID-1: PQ2.2 PR2.1 PR5.2
PSID-2: PQ1.2 PQ2.1 PR3.2
PSID-3: PQ1.3 PR1.1
PTP_DIS#: JTP.6 RE28.2 RX4.2 UE1.38
PWR_PWM_LED: Q6102.1 R6107.2
PWR_PWM_LED#: R6104.2 UE1.92
PWR_PWM_LED_R#: Q6102.2 Q6105.1 R6104.1
REMOTE1+: C2500.1 C2502.1 Q2407.1 Q2407.2 U2407.2
REMOTE1-: C2500.2 C2502.2 Q2407.3 U2407.3
REMOTE2+: C2504.1 C2505.1 Q2408.1 Q2408.2 U2407.4
REMOTE2-: C2504.2 C2505.2 Q2408.3 U2407.5
RING2: LA10.2 RA1109.1 UA1.17
RING2_R: JIO1.3 JIO1.4 LA10.1
RREF: RR1.1 UR1.1
RTC_RST#: CC22.1 R1089.2 RC35.2 USOC1.C12
RTC_TEST#: CC20.2 JDB1.13 R1088.2 RC34.2 USOC1.C11
SATA_LED: EC6104.1 Q6104.1 R6108.1
SATA_LED#_B: Q6103.1 Q6104.2 R6106.2
SATA_LED#_R: Q6105.2 R6110.2 RD15.2
SATA_LED#_SOC: QC2.3 RC18.2 USOC1.AY12
SATA_LED_R: LED2.2 R6108.2
SATA_PRX_DTX_N0: CS34.2 JHDD.8
SATA_PRX_DTX_N0_C: CS34.1 USOC1.AV16
SATA_PRX_DTX_N1: CS14.1 JODD1.5
SATA_PRX_DTX_N1_C: CS14.2 USOC1.BA16
SATA_PRX_DTX_P0: CS31.2 JHDD.7
SATA_PRX_DTX_P0_C: CS31.1 USOC1.AU16
SATA_PRX_DTX_P1: CS15.1 JODD1.6
SATA_PRX_DTX_P1_C: CS15.2 USOC1.AY16
SATA_PTX_DRX_N0: CS32.2 JHDD.10
SATA_PTX_DRX_N0_C: CS32.1 USOC1.BG7
SATA_PTX_DRX_N1: CS9.1 JODD1.3
SATA_PTX_DRX_N1_C: CS9.2 USOC1.BF10
SATA_PTX_DRX_P0: CS30.2 JHDD.11
SATA_PTX_DRX_P0_C: CS30.1 USOC1.BF6
SATA_PTX_DRX_P1: CS8.1 JODD1.2
SATA_PTX_DRX_P1_C: CS8.2 USOC1.BD10
SATA_RCOMPN: RC12.1 USOC1.AT18
SATA_RCOMPP: RC12.2 USOC1.AU18
SD3_RCOMP: RC59.1 USOC1.BF26
SD_CD#: CR9.1 JREAD.10 UR1.13
SD_CMD: CR11.1 JREAD.2 UR1.18
SD_D0: JREAD.7 UR1.11
SD_D1: JREAD.8 UR1.10
SD_D2: JREAD.9 UR1.21
SERIRQ: R23.1 UE1.3
SIO_SLP_S3#: CE27.1 R24.1 UE1.6
SIO_SLP_S4#: CE28.1 R25.1 UE1.123
SLEEVE: LA7.2 QA1.3 RA53.1 UA1.18
SLEEVE_R: JIO1.5 JIO1.6 LA7.1
SNB_3V: PC114.1 PR109.2
SNB_5V: PC115.1 PR110.2
SNB_CHG: PC716.1 PR721.2
SOC_KBRST#: R3.2 R22.1 USOC1.B18
SOC_LID_OUT#: R4.2 R26.1 USOC1.C17
SOC_ODD_DA#: DX2.2 RP63.4 USOC1.BE3
SOC_SATALED#: Q6103.3 Q6105.3 QC2.1 R6106.1 RX5.2
SOC_SCI#: R8.2 R29.1 USOC1.BA12
SOC_SERIRQ: R23.2 USOC1.BG13
SOC_SMI#: R7.2 R31.1 USOC1.C15
SOC_SPI_CLK: RP67.6 USOC1.C22
SOC_SPI_CS0#: RP67.8 USOC1.C23
SOC_SPI_MISO: RP67.7 USOC1.B22
SOC_SPI_MOSI: RP67.5 USOC1.A21
SOC_SPKR: DA8.3 USOC1.BH12
SOC_SUS_STAT#: T8.1(TP-1) USOC1.G18
SOC_TP_INT#: QE9.3 RE34.2 USOC1.C19
SOC_TS_INT#: QE12.3 RX41.2 USOC1.AU32
SPI_CLK: RC39.1 RP67.3 UC8.6
SPI_CS0#: RC36.2 RP67.1 UC8.1
SPI_HOLD#: RC37.2 UC8.7
SPI_MISO: RP67.2 UC8.2
SPI_MOSI: RP67.4 UC8.5
SPI_WP#: RC38.2 UC8.3
SPK_L+_CONN: CA30.1 JSPK.3 LA5.1
SPK_L-_CONN: CA29.1 JSPK.4 LA6.1
SPK_R+_CONN: CA32.1 JSPK.1 LA3.1
SPK_R-_CONN: CA31.1 JSPK.2 LA4.1
SPOK: PR106.2 PR308.1 PR400.1 PU100.7 UE1.18
SUSCLK_R: JNGFF.42 RM8.1
SUSP: Q8.1 Q70.2 Q71.2 Q2307.2 Q2308.2 R10.2
SUSP#: PR208.1 PR300.1 PR409.1 Q8.2 R16.1 R926.1 R927.2 R1055.2 R1056.2 UE1.116
SW_1.35VP: PC207.2 PL200.2 PQ201.1 PQ201.2 PQ201.3 PQ203.5 PR202.1 PU200.16
SYSON: CE26.1 PR207.1 UE1.95
THERMAL_SMB_CK2: R2449.2 RE22.1 U2407.10
THERMAL_SMB_DA2: R2451.2 RE23.1 U2407.9
TMDS_L_TX0N: JHDMI1.9 R2360.2 RC71.2
TMDS_L_TX0P: JHDMI1.7 R2361.2 RC71.1
TMDS_L_TX1N: JHDMI1.6 R2362.2 RC72.2
TMDS_L_TX1P: JHDMI1.4 R2363.2 RC72.1
TMDS_L_TX2N: JHDMI1.3 R2365.2 RC73.1
TMDS_L_TX2P: JHDMI1.1 R2364.2 RC73.2
TMDS_L_TXCN: JHDMI1.12 R2358.2 RC70.2
TMDS_L_TXCP: JHDMI1.10 R2359.2 RC70.1
TMDS_TX0N: CX14.1 R1073.1 R2360.1
TMDS_TX0P: CX15.1 R1074.1 R2361.1
TMDS_TX1N: CX16.1 R1075.1 R2362.1
TMDS_TX1P: CX17.1 R1076.1 R2363.1
TMDS_TX2N: CX18.1 R1077.1 R2365.1
TMDS_TX2P: CX19.1 R1078.1 R2364.1
TMDS_TXCN: CX12.1 R1071.1 R2358.1
TMDS_TXCP: CX13.1 R1072.1 R2359.1
TON_1.35VP: PR205.2 PU200.9
TOUCH_RST#: RX1.1 UE1.29
TOUCH_RST#_R: JEDP.38 RX1.2 RX24.2
TP2_CORE_VCC_S0IX: T112.1(TP-1) USOC1.AA22
TP_CLK: DE3.3 JTP.8 RE9.2 UE1.87
TP_CORE_V1P05_S4: T195.1(TP-1) USOC1.AF30
TP_DATA: DE3.2 JTP.7 RE10.2 UE1.88
TP_EN: UE1.85 UE4.3
TP_INT#: JTP.5 QE9.1 RE20.2 RE29.2
TS_EN: UE1.19 UX3.3
TS_INT#: JEDP.37 QE12.1 R5205.1 RX42.2
TXE_DBG: QC1.2 UE1.99
UG_3V: PQ101.4 PU100.10
UG_5V: PQ102.4 PU100.16
UGATE1: PR528.1 PU500.17
UGATE1-1: PQ503.1 PR528.2
UGATEG1: PR506.1 PU500.25
UGATEG1-1: PQ501.1 PR506.2
USB3_REXT0: RC40.1 USOC1.M12
USB3RN2_JUSB1_R: DI1.1 DI1.10 JUSB1.5 R2367.1
USB3RP2_JUSB1_R: DI1.2 DI1.9 JUSB1.6 R2366.1
USB3TN2_JUSB1_R: DI1.4 DI1.7 JUSB1.8 R2369.1
USB3TP2_JUSB1_R: DI1.5 DI1.6 JUSB1.9 R2368.1
USB20_CAM_N2_R: JEDP.30 RX21.1
USB20_CAM_P2_R: JEDP.31 RX22.1
USB20_CPU_N3: U58.15 USOC1.H10
USB20_CPU_P3: U58.16 USOC1.K10
USB20_CR_N3_R: RR5.1 UR1.2
USB20_CR_P3_R: RR4.1 UR1.3
USB20_HUB_N1: JEDP.34 U58.10
USB20_HUB_N2: JNGFF.5 U58.8
USB20_HUB_N3: LI6.4 U58.6
USB20_HUB_N4: RR5.2 U58.4
